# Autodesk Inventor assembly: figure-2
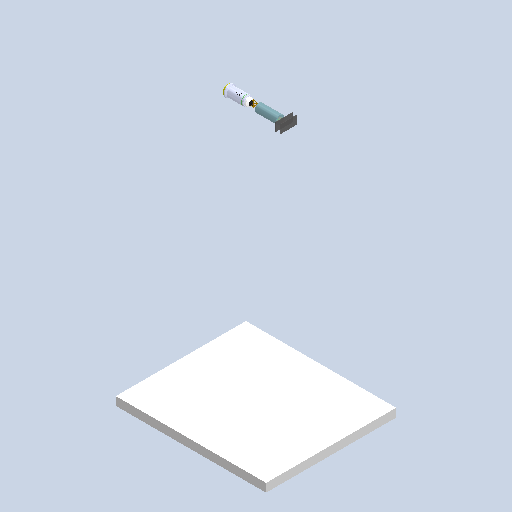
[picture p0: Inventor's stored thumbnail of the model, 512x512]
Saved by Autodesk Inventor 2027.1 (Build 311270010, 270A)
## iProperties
Created: 2026-09
Part Number: figure-2
Document SubType Name: Assembly
Designer: dunge
Author: dunge
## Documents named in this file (3)
- C:\Users\dunge\OneDrive\Documents\Inventor\Inventor\Inventor\simplified-drawings\figure-2.iam
- C:\Users\dunge\OneDrive\Documents\Inventor\Inventor\Inventor\simplified-drawings\imports\N16XLWD-PF-Solidworks\N16XLWD-PF-Solidworks.ipt
- C:\Users\dunge\OneDrive\Documents\Inventor\Inventor\Inventor\simplified-drawings\figure-2-path.ipt
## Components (2 placed, 2 different names)
1. N16XLWD-PF-Solidworks:1 — Mate:1, Mate:2
2. figure-2-path:1 — Mate:1, Mate:2
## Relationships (2: Mate 2)
- Mate:1: N16XLWD-PF-Solidworks:1 ↔ figure-2-path:1
- Mate:2: N16XLWD-PF-Solidworks:1 ↔ figure-2-path:1
## Named parameters: Finish1_Area = 3.16692 mm
